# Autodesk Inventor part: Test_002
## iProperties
Created: 2009-08
Part Number: Test_002
Document SubType Name: Modeling
Designer: 10172392
Density: 1 g/cm^3
Author: 10172392
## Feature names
1. Extrusion1
